(* Logix 5000 project; controller logix5561 vendor 1 type 14 code 54 rev 19.11; software revision 19.01 *)

TASK MainTask (continuous, watchdog 500 ms) : MainProgram

MODULES
   Local : vendor 1 type 14 code 54 (ICP 0, rev 19.11)
      EIP : 1756-ENBT (ICP 1, Ethernet 192.168.16.199, rev 6.1)
         Mitsubishi_Inverter : ETHERNET-MODULE (Ethernet 192.168.16.22, rev 1.1, Output RPI 10 ms)   // Conveyor #6 first roller
END_MODULES

ADD_ON_INSTRUCTION FRA7NWIE_Generic_Default_IO   (* revision 1.0 *)
// Simple interface for generic default IO mapping that uses Input Assembly Instance 150 and Output Assembly Instance 100.
VAR_IN_OUT
   I_Data : INT[2]; {required}   // Input data
   O_Data : INT[2]; {required}   // Output data
END_VAR
VAR_INPUT
   RunStop : BOOL; {access Read Only, required}   // Run (0) or Stop (1)
   Forward : BOOL; {access Read Only, required}   // Run forward direction
   Reverse : BOOL; {required}   // Run reverse direction
   Reset : BOOL; {required}   // Reset the fault
   FrequencyCommand : INT; {access Read Only, required}   // Frequency command/reference
END_VAR
VAR_OUTPUT
   RunningStopped : BOOL; {access Read Only, visible}   // Running (1) or Stopped (0)
   RunningForward : BOOL; {visible}   // Running forward direction
   RunningReverse : BOOL; {visible}   // Running reverse direction
   UpToFrequency : BOOL; {access Read Only, visible}   // Up to frequency
   Alarm : BOOL; {access Read Only, visible}   // Alarm or Trip
   OutputFrequency : INT; {access Read Only, visible}   // Output/feedback frequency
END_VAR

ROUTINE Logic   (* ladder *)
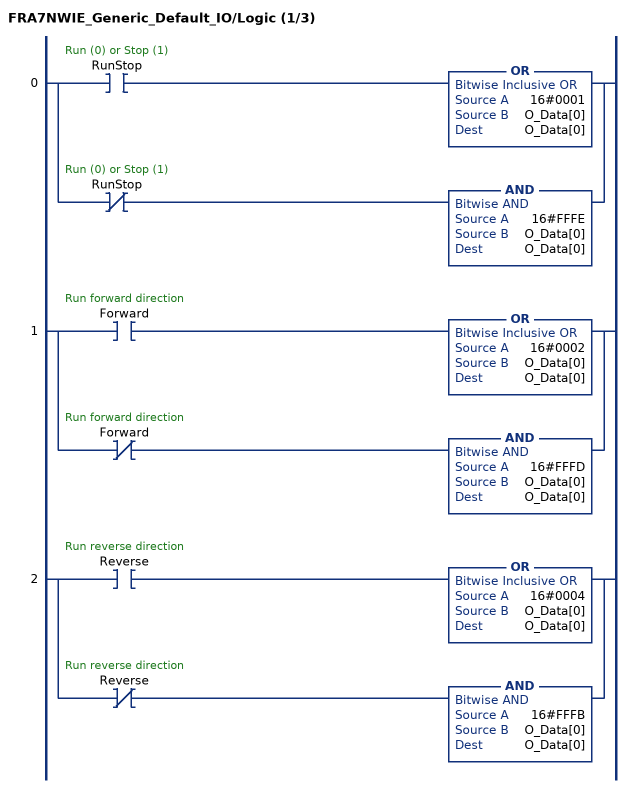
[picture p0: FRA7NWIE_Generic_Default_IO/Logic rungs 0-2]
   0: [XIC(RunStop) OR(16#0001,O_Data[0],O_Data[0]) ,XIO(RunStop) AND(16#FFFE,O_Data[0],O_Data[0]) ];
   1: [XIC(Forward) OR(16#0002,O_Data[0],O_Data[0]) ,XIO(Forward) AND(16#FFFD,O_Data[0],O_Data[0]) ];
   2: [XIC(Reverse) OR(16#0004,O_Data[0],O_Data[0]) ,XIO(Reverse) AND(16#FFFB,O_Data[0],O_Data[0]) ];
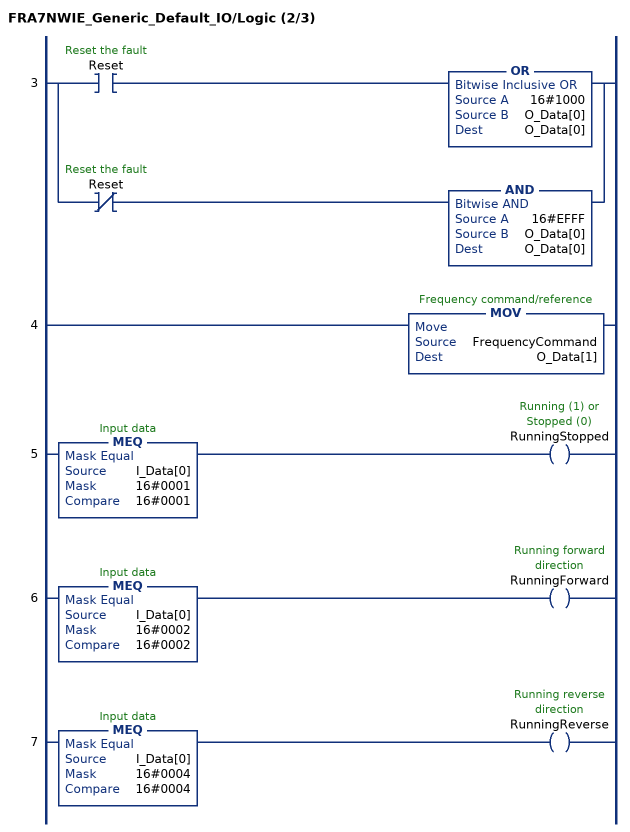
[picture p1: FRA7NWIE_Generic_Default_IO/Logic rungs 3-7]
   3: [XIC(Reset) OR(16#1000,O_Data[0],O_Data[0]) ,XIO(Reset) AND(16#EFFF,O_Data[0],O_Data[0]) ];
   4: MOV(FrequencyCommand,O_Data[1]);
   5: MEQ(I_Data[0],16#0001,16#0001)OTE(RunningStopped);
   6: MEQ(I_Data[0],16#0002,16#0002)OTE(RunningForward);
   7: MEQ(I_Data[0],16#0004,16#0004)OTE(RunningReverse);
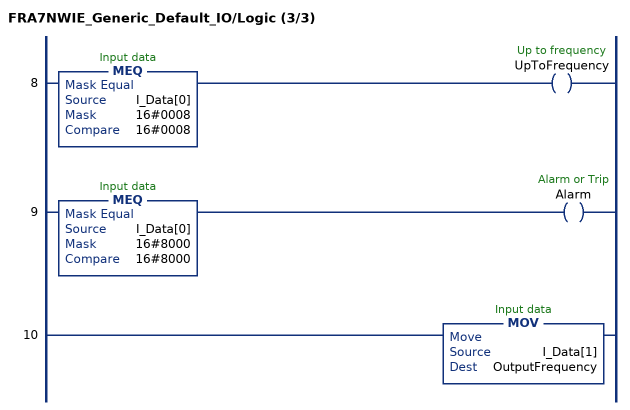
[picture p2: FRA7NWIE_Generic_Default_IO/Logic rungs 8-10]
   8: MEQ(I_Data[0],16#0008,16#0008)OTE(UpToFrequency);
   9: MEQ(I_Data[0],16#8000,16#8000)OTE(Alarm);
   10: MOV(I_Data[1],OutputFrequency);
END_ROUTINE
END_ADD_ON_INSTRUCTION

VAR_GLOBAL   (* controller tags *)
   freq_cmd : INT;   // Frequency command (hertz)
   fwd : BOOL;   // Forward direction
   generic_aoi : FRA7NWIE_Generic_Default_IO;
   reset : BOOL;   // Reset alarm or fault
   rev : BOOL;   // Reverse direction
   run_stop : BOOL;   // 0 = Run, 1 = Stop
END_VAR

PROGRAM MainProgram   (* main routine MainRoutine *)

ROUTINE MainRoutine   (* ladder *)
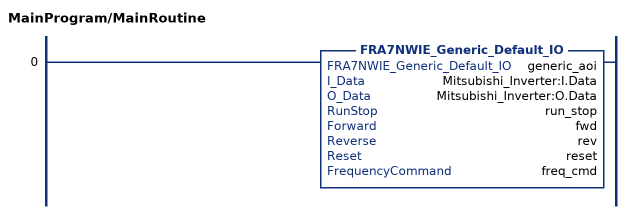
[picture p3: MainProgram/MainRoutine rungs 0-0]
   0: FRA7NWIE_Generic_Default_IO(generic_aoi,Mitsubishi_Inverter:I.Data,Mitsubishi_Inverter:O.Data,run_stop,fwd,rev,reset,freq_cmd);
END_ROUTINE
END_PROGRAM
